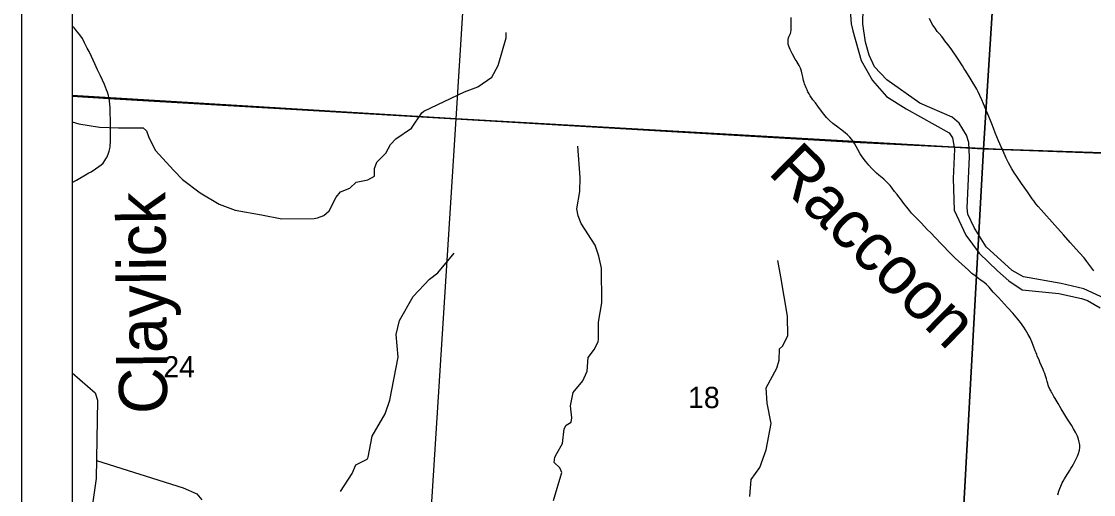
# Model space of a CAD drawing. Extents: x 0 to 34, y 0 to 22.
# Drawn here: x 2 to 4.109, y 15.341 to 16.271 of the extents above; entities that cross this region are included whole.
import ezdxf

# ---------------------------------------------------------------- set-up
doc = ezdxf.new("R2010")
doc.units = 0
for name, color, linetype in [('Default', 7, 'Continuous'), ('GM_X_County_Road', 7, 'Continuous'), ('GM_X_Major_River', 7, 'Continuous'), ('GM_X_Major_River_Text', 7, 'Continuous'), ('GM_X_Minor_River', 7, 'Continuous'), ('GM_X_Minor_River_Text', 7, 'Continuous'), ('GM_X_Section', 7, 'Continuous'), ('GM_X_Section_Text', 7, 'Continuous'), ('GM_X_Township_Road', 7, 'Continuous'), ('SH_Data', 7, 'Continuous'), ('SH_Text', 7, 'Continuous')]:
    doc.layers.add(name, color=color, linetype=linetype)

msp = doc.modelspace()

# ---------------------------------------------------------------- linework, layer by layer
at = {"layer": 'Default'}
msp.add_lwpolyline([(2.1, 20.9), (2.1, 16.1239), (2.1721, 16.1195), (3.6368, 16.0331), (3.9292, 16.0191), (4.6644, 15.9921)], dxfattribs=at)
for points in [[(2.1, 17.1515), (2.1, 16.1254), (2.8549, 16.0795), (2.9191, 17.1007)], [(2.1, 16.1254), (2.1, 15.1095), (2.7909, 15.0689), (2.8549, 16.0795)], [(2.1, 16.1239), (2.1, 14.1), (4.8164, 14.1), (4.8734, 15.0246), (4.8987, 15.3279), (4.9458, 15.9099), (4.9525, 15.9829), (4.6644, 15.9921), (3.9292, 16.0191), (3.6368, 16.0331), (2.1721, 16.1195)]]:
    msp.add_lwpolyline(points, close=True, dxfattribs=at)
at = {"layer": 'GM_X_County_Road'}
for points in [[(2.1724, 16.1189), (2.1719, 16.1211), (2.1711, 16.125), (2.1692, 16.1314), (2.1675, 16.1364), (2.1632, 16.147), (2.1554, 16.1636), (2.1499, 16.1754), (2.1444, 16.1872), (2.1376, 16.2017), (2.133, 16.2114), (2.1296, 16.2182), (2.1243, 16.2289), (2.12, 16.2369), (2.1151, 16.2442), (2.1118, 16.2484), (2.1084, 16.2525), (2.1043, 16.2575), (2.1013, 16.261), (2.1, 16.2623)], [(3.9294, 16.0186), (3.9217, 16.0361), (3.9155, 16.0517), (3.912, 16.0609), (3.9085, 16.0696), (3.906, 16.0758), (3.8923, 16.1087), (3.8889, 16.1165), (3.8851, 16.1252), (3.8819, 16.132), (3.8791, 16.1375), (3.8755, 16.144), (3.8703, 16.1526), (3.8664, 16.1589), (3.8574, 16.173), (3.8544, 16.1777), (3.8507, 16.1835), (3.8423, 16.1966), (3.8396, 16.2007), (3.8286, 16.2165), (3.8223, 16.2254), (3.8166, 16.2324), (3.8136, 16.2364), (3.8101, 16.2408), (3.8051, 16.2469), (3.8014, 16.2512), (3.7973, 16.2573), (3.793, 16.2636), (3.789, 16.2704), (3.7863, 16.2764)], [(2.1, 15.9538), (2.1085, 15.9586), (2.1293, 15.9711), (2.1326, 15.9729), (2.1369, 15.9753), (2.1457, 15.9809), (2.1524, 15.9853), (2.1569, 15.9888), (2.1605, 15.9923), (2.1643, 15.9974), (2.1663, 16.0006), (2.1679, 16.0033), (2.1708, 16.0096), (2.1728, 16.0156), (2.1739, 16.0206), (2.1743, 16.0238), (2.1747, 16.0268), (2.1748, 16.028), (2.1749, 16.0327), (2.1751, 16.0368), (2.1752, 16.0424), (2.1751, 16.0512), (2.1751, 16.0585), (2.175, 16.0635), (2.175, 16.0685), (2.175, 16.0728), (2.1749, 16.0804), (2.1748, 16.0871), (2.1747, 16.0919), (2.1745, 16.0965), (2.1743, 16.1014), (2.1739, 16.1077), (2.1731, 16.1147), (2.1724, 16.1189)], [(4.1094, 15.7806), (4.1036, 15.7883), (4.0953, 15.7991), (4.0902, 15.8058), (4.0813, 15.8159), (4.063, 15.836), (4.0497, 15.851), (4.0329, 15.8703), (4.0057, 15.9006), (3.9999, 15.9071), (3.9953, 15.9123), (3.9913, 15.9178), (3.9881, 15.9222), (3.9789, 15.9356), (3.9726, 15.9447), (3.9671, 15.9524), (3.9619, 15.9597), (3.9577, 15.9656), (3.9532, 15.9722), (3.948, 15.9807), (3.9415, 15.9927), (3.9369, 16.0021), (3.9327, 16.0111), (3.9294, 16.0186)]]:
    msp.add_lwpolyline(points, dxfattribs=at)
at = {"layer": 'GM_X_Major_River'}
for points in [[(4.1313, 15.7261), (4.0896, 15.7453), (4.0452, 15.7557), (3.9709, 15.7684), (3.9489, 15.7808), (3.8976, 15.8277), (3.8813, 15.8538), (3.874, 15.8656), (3.8615, 15.8921), (3.8599, 15.9046), (3.8646, 16.0048), (3.8633, 16.0325), (3.8591, 16.0469), (3.8447, 16.0707), (3.831, 16.0825), (3.7669, 16.1103), (3.702, 16.156), (3.6777, 16.1817), (3.6674, 16.2041), (3.6601, 16.2298), (3.6547, 16.2662), (3.656, 16.3289)], [(3.6292, 16.3018), (3.632, 16.2662), (3.635, 16.2525), (3.6515, 16.1941), (3.6743, 16.1547), (3.7017, 16.123), (3.74, 16.0988), (3.825, 16.0517), (3.8315, 16.0419), (3.835, 16.0199), (3.8325, 15.9618), (3.8349, 15.8999), (3.8574, 15.8507), (3.8837, 15.8155), (3.9201, 15.7803), (3.9422, 15.7607), (3.9687, 15.7433), (4.0403, 15.7356), (4.0851, 15.7259), (4.0972, 15.7222), (4.1219, 15.7074)]]:
    msp.add_lwpolyline(points, dxfattribs=at)
at = {"layer": 'GM_X_Minor_River'}
for points in [[(2.1, 16.0733), (2.1132, 16.0691), (2.1533, 16.0631), (2.1909, 16.0616), (2.2394, 16.0616), (2.2458, 16.0556), (2.2496, 16.0442), (2.2632, 16.0176), (2.2996, 15.9777), (2.3167, 15.9602), (2.3515, 15.9336), (2.389, 15.9113), (2.4201, 15.8995), (2.4721, 15.8904), (2.5122, 15.8825), (2.5759, 15.8833), (2.5824, 15.8849), (2.5949, 15.8891), (2.6055, 15.8982), (2.6191, 15.9252), (2.6279, 15.9355), (2.6461, 15.9427), (2.6586, 15.9549), (2.6813, 15.9595), (2.6946, 15.9663), (2.6942, 15.9819), (2.6988, 15.9941), (2.717, 16.012), (2.7257, 16.0287), (2.7363, 16.0398), (2.767, 16.0607), (2.7875, 16.0912), (2.7913, 16.0946), (2.8717, 16.1323), (2.8978, 16.1422), (2.9251, 16.1609), (2.9377, 16.1841), (2.9532, 16.2381), (2.9536, 16.2489)], [(3.0463, 15.3291), (3.0628, 15.3843), (3.0587, 15.393), (3.0481, 15.4036), (3.0492, 15.4143), (3.0534, 15.4215), (3.0644, 15.4413), (3.0674, 15.4702), (3.0712, 15.477), (3.0814, 15.4831), (3.0826, 15.4915), (3.0799, 15.5151), (3.0849, 15.5413), (3.1042, 15.5645), (3.1126, 15.5832), (3.1149, 15.6102), (3.1274, 15.6265), (3.1342, 15.6414), (3.135, 15.6452), (3.135, 15.6798), (3.1414, 15.7178), (3.1411, 15.7858), (3.1354, 15.8094), (3.1286, 15.8311), (3.1009, 15.8733), (3.0949, 15.8888), (3.0926, 15.9025), (3.0983, 15.9364), (3.0987, 15.9641), (3.0942, 16.0253)], [(2.6278, 15.3468), (2.6504, 15.3819), (2.6576, 15.3994), (2.68, 15.4105), (2.6823, 15.4143), (2.6899, 15.4557), (2.7156, 15.4991), (2.7248, 15.5261), (2.7411, 15.6109), (2.7369, 15.655), (2.7434, 15.6831), (2.7703, 15.7299), (2.8029, 15.7638), (2.8189, 15.7768), (2.8511, 15.8152)], [(3.4329, 15.3367), (3.4351, 15.3702), (3.4525, 15.3942), (3.4647, 15.4288), (3.4749, 15.4801), (3.467, 15.5204), (3.4651, 15.5505), (3.4856, 15.5893), (3.4901, 15.6049), (3.4909, 15.6269), (3.4973, 15.6326), (3.5072, 15.6528), (3.5068, 15.6916), (3.4936, 15.7687), (3.4876, 15.8007)], [(2.1, 15.5801), (2.145, 15.5405), (2.1497, 15.5265), (2.1467, 15.3721)], [(2.1474, 15.4078), (2.3179, 15.3542), (2.3448, 15.3418)], [(2.1467, 15.3721), (2.1404, 15.3265), (2.1404, 15.314), (2.1435, 15.309), (2.1329, 15.2923), (2.1287, 15.2759), (2.1182, 15.2519), (2.1148, 15.2307), (2.111, 15.2238), (2.1, 15.1941)], [(2.3448, 15.3418), (2.3547, 15.3301)]]:
    msp.add_lwpolyline(points, dxfattribs=at)
at = {"layer": 'GM_X_Section'}
for points in [[(2.9191, 17.1007), (3.9555, 17.0086), (3.8924, 16.0203), (2.8549, 16.0795)], [(5.0081, 16.9831), (4.9447, 15.9846), (3.8924, 16.0203), (3.9555, 17.0086), (4.4681, 17.0085)], [(2.8549, 16.0795), (3.8924, 16.0203), (3.8368, 15.0128), (2.7909, 15.0689)], [(3.8924, 16.0203), (4.9447, 15.9846), (4.9568, 15.9843), (4.8777, 14.9601), (3.8368, 15.0128)]]:
    msp.add_lwpolyline(points, close=True, dxfattribs=at)
at = {"layer": 'GM_X_Township_Road'}
for points in [[(3.5255, 16.1912), (3.5221, 16.1966), (3.5168, 16.2063), (3.5121, 16.2155), (3.5092, 16.222), (3.5081, 16.2263), (3.5078, 16.2307), (3.508, 16.2352), (3.5086, 16.2383), (3.5101, 16.2418), (3.5115, 16.2446), (3.5127, 16.2467), (3.5136, 16.2496), (3.5141, 16.2532), (3.5142, 16.2599), (3.514, 16.2705), (3.5139, 16.2785)], [(3.6359, 16.0342), (3.6332, 16.0383), (3.6294, 16.0431), (3.6251, 16.0475), (3.62, 16.0519), (3.6112, 16.0587), (3.6092, 16.0602), (3.6056, 16.0627), (3.5957, 16.0702), (3.5892, 16.076), (3.5836, 16.0819), (3.5785, 16.0882), (3.5719, 16.0972), (3.5666, 16.1041), (3.5616, 16.1105), (3.5566, 16.1168), (3.5541, 16.1205), (3.5517, 16.1241), (3.5493, 16.1284), (3.5471, 16.1322), (3.5452, 16.1363), (3.5433, 16.1401), (3.5404, 16.1477), (3.5396, 16.1508), (3.5386, 16.1543), (3.5378, 16.1578), (3.537, 16.1616), (3.5358, 16.167), (3.5341, 16.173), (3.5321, 16.1785), (3.5295, 16.1842), (3.526, 16.1903), (3.5255, 16.1912)], [(4.0385, 15.3404), (4.0408, 15.3473), (4.0426, 15.3523), (4.0443, 15.3573), (4.0469, 15.3636), (4.0488, 15.3669), (4.0515, 15.3717), (4.0568, 15.3802), (4.0594, 15.3843), (4.0614, 15.3875), (4.0644, 15.3922), (4.0666, 15.3959), (4.0694, 15.4007), (4.0741, 15.4094), (4.0773, 15.4161), (4.0792, 15.4213), (4.0809, 15.4279), (4.0816, 15.4333), (4.0815, 15.4382), (4.0808, 15.4436), (4.0793, 15.4496), (4.0771, 15.4553), (4.0741, 15.4618), (4.0696, 15.4697), (4.0656, 15.4768), (4.0577, 15.4887), (4.0453, 15.5089), (4.0392, 15.5197), (4.033, 15.5297), (4.0305, 15.5334), (4.0272, 15.5399), (4.0264, 15.5415), (4.0252, 15.5437), (4.023, 15.548), (4.0219, 15.5501), (4.0208, 15.5521), (4.0196, 15.5556), (4.0187, 15.5591), (4.0177, 15.5628), (4.0161, 15.5682), (4.0144, 15.574), (4.0128, 15.5787), (4.0113, 15.5824), (4.0096, 15.5868), (4.0034, 15.6009), (4.0015, 15.6055), (3.9993, 15.6104), (3.9982, 15.6131), (3.997, 15.6161), (3.9956, 15.6193), (3.994, 15.6232), (3.9908, 15.6321), (3.9877, 15.6406), (3.9838, 15.649), (3.9805, 15.6552), (3.9778, 15.6596), (3.9751, 15.6642), (3.9714, 15.6695), (3.9681, 15.6744), (3.9648, 15.6786), (3.9597, 15.6852), (3.9501, 15.6974), (3.9397, 15.7084), (3.9218, 15.7283), (3.9114, 15.7387), (3.9032, 15.7483), (3.898, 15.7538), (3.893, 15.7579), (3.8861, 15.7629), (3.8826, 15.7655), (3.8793, 15.7681), (3.876, 15.7705), (3.8716, 15.7739), (3.8697, 15.7754), (3.8641, 15.7803), (3.8627, 15.7815), (3.8563, 15.7874), (3.8365, 15.8053), (3.8291, 15.8128), (3.8083, 15.8342), (3.7878, 15.8556), (3.7821, 15.8613), (3.7753, 15.8685), (3.7701, 15.8739), (3.7636, 15.8806), (3.7563, 15.8882), (3.7509, 15.894), (3.7466, 15.899), (3.7413, 15.9056), (3.7381, 15.9098), (3.7356, 15.9131), (3.7289, 15.922), (3.726, 15.9257), (3.7223, 15.9304), (3.7175, 15.9366), (3.7128, 15.943), (3.7086, 15.9483), (3.7035, 15.9537), (3.6961, 15.9603), (3.6867, 15.9684), (3.682, 15.9725), (3.6771, 15.9772), (3.6719, 15.9825), (3.6669, 15.9879), (3.66, 15.9963), (3.6538, 16.0045), (3.6499, 16.0106), (3.645, 16.0191), (3.6383, 16.0307), (3.637, 16.0326), (3.6359, 16.0342)]]:
    msp.add_lwpolyline(points, dxfattribs=at)
at = {"layer": 'SH_Data'}
for p, q in [((2, 21), (2, 14)), ((2.1, 20.9), (2.1, 14.1))]:
    msp.add_line(p, q, dxfattribs=at)
at = {"layer": 'SH_Text'}
msp.add_lwpolyline([(2.1, 20.9), (2.1, 14.1), (8.0885, 14.1)], dxfattribs=at)

# ---------------------------------------------------------------- texts
at = {"layer": 'GM_X_Major_River_Text'}
msp.add_text('Raccoon', height=0.0947, rotation=315.5119, dxfattribs=at).set_placement((3.4661, 15.9724))
at = {"layer": 'GM_X_Minor_River_Text'}
msp.add_text('Claylick', height=0.0947, rotation=90.5134, dxfattribs=at).set_placement((2.2869, 15.4994))
at = {"layer": 'GM_X_Section_Text'}
for s, p in [('24', (2.2791, 15.5709)), ('18', (3.3112, 15.5106))]:
    msp.add_text(s, height=0.04186, rotation=0, dxfattribs=at).set_placement(p)

doc.saveas('drawing.dxf')
